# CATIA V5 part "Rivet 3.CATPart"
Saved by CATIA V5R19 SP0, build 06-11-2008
Part number: Rivet 3
Bounding box of the stored display mesh (mm): x -4.999 to 4.999, y -2.101 to 10.101, z -4.999 to 4.999
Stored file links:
  G:\EU_thinkMotion\CFAO_2010\St2M_groupe2\St2M_groupe2\csayed\csayed\csayed\Rivet 3.CATPart
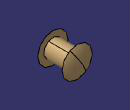
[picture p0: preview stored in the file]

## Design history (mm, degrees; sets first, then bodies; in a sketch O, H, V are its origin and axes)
Body1 (main body)
  Sketch1 on yz-plane, origin (0, 0, 0), H (0, 1, 0), V (0, 0, 1)
    line L1 (0, 3) -> (0, 5)
    arc A1 centre (4.899, 0) radius 7 from (0, 5) to (-2.101, 0) ccw
    point P2 (4.899, 0)
    line L2 (0, 3) -> (8, 3)
    line L3 (8, 5) -> (8, 3)
    arc A2 centre (3.101, 0) radius 7 from (8, 5) to (10.101, 0) cw
    point P6 (3.101, 0)
    line L4 (-2.101, 0) -> (10.101, 0)
    point P7 (-2.101, 0)
    distance P2 A1 = 7
    distance L2 H = 3
    distance P6 A2 = 7
    vertical: L1 V, L3 V
    horizontal: L2 H, L4 H
    coincidence: P7 H
  Shaft1: profile Sketch1, axis Sketch1.L4, angle 360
